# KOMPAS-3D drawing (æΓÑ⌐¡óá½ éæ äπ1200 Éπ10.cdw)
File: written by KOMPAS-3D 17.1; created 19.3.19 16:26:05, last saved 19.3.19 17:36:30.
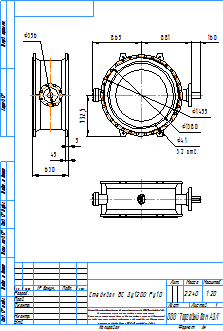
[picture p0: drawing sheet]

Sheet 1: A4, portrait

Title block, sheet 1: name: Стейнвал ВС Ду1200 Ру10; material: Сталь 20  ГОСТ 1050-88; mass: 2240; sheets: 1; sheet format: A4; stored path: C:\Users\kka\KOMPAS_Work\!Trash\Стейнвал ВС двухэксцентрик\KOMPAS 2D\Стейнвал ВС Ду1200 Ру10.cdw

Views: Проекционный вид 2, Проекционный вид 3
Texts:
  kka
  adl
  Рама для чертежей
  Лит-Масса-Масштаб
  Материал-Предприятие
  Масштаб
  Изм.
  Лист
  № докум.
  Подп.
  Дата
  Лит.
  Разраб.
  Пров.
  Т.контр.
  Листов
  Внимание! Данный продукт является объектом авторского права ООО «Торговый Дом АДЛ».
  Запрещается изменение, копирование, распространение
  (в том числе путем копирования на другие сайты и ресурсы в Интернете)
  или любое иное использование информации и объектов без предварительного
  согласия правообладателя (ООО «Торговый Дом АДЛ»).
  Н.контр.
  Утв.
  ООО "Торговый дом АДЛ"
  Изменение
  Номер документа
  Подпись
  Обозначение документа
  Наименование изделия
  Масса изделия по ГОСТ 2.109-73
  Порядковый номер листа
  Общее количество листов в документе
  Характер работы, выполненной лицом, подписавшим документ
  Наименование или индекс предприятия, выпускающего документ
  Инв. № подл.
  Подп. и дата
  Взам. инв. №
  Инв. № дубл.
  Инвентарный номер подлинника по ГОСТ 2.501-68
  Подпись принявшего подлинник в отдел технической документации
  Инвентарный номер подлинника, взамен которого выпущен данный подлинник
  Инвентарный номер дубликата по ГОСТ 2.502-68
  Подпись принявшего дубликат в отдел технической документации
  Справ. №
  Перв. примен.
  Обозначение документа, взамен или на основании которого выпущен данный документ
  Обозначение документа, в котором впервые записан данный документ
  Подпись лица, копировавшего чертеж
  Обозначение формата листа
  !Рама для чертежа
Dimensions and other numbers on the sheet: 630; 45; 5; 356; 881; 160; 865; 732,5; 1455; 1380; 41; 32 отв.; 1:20; 1; 2240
